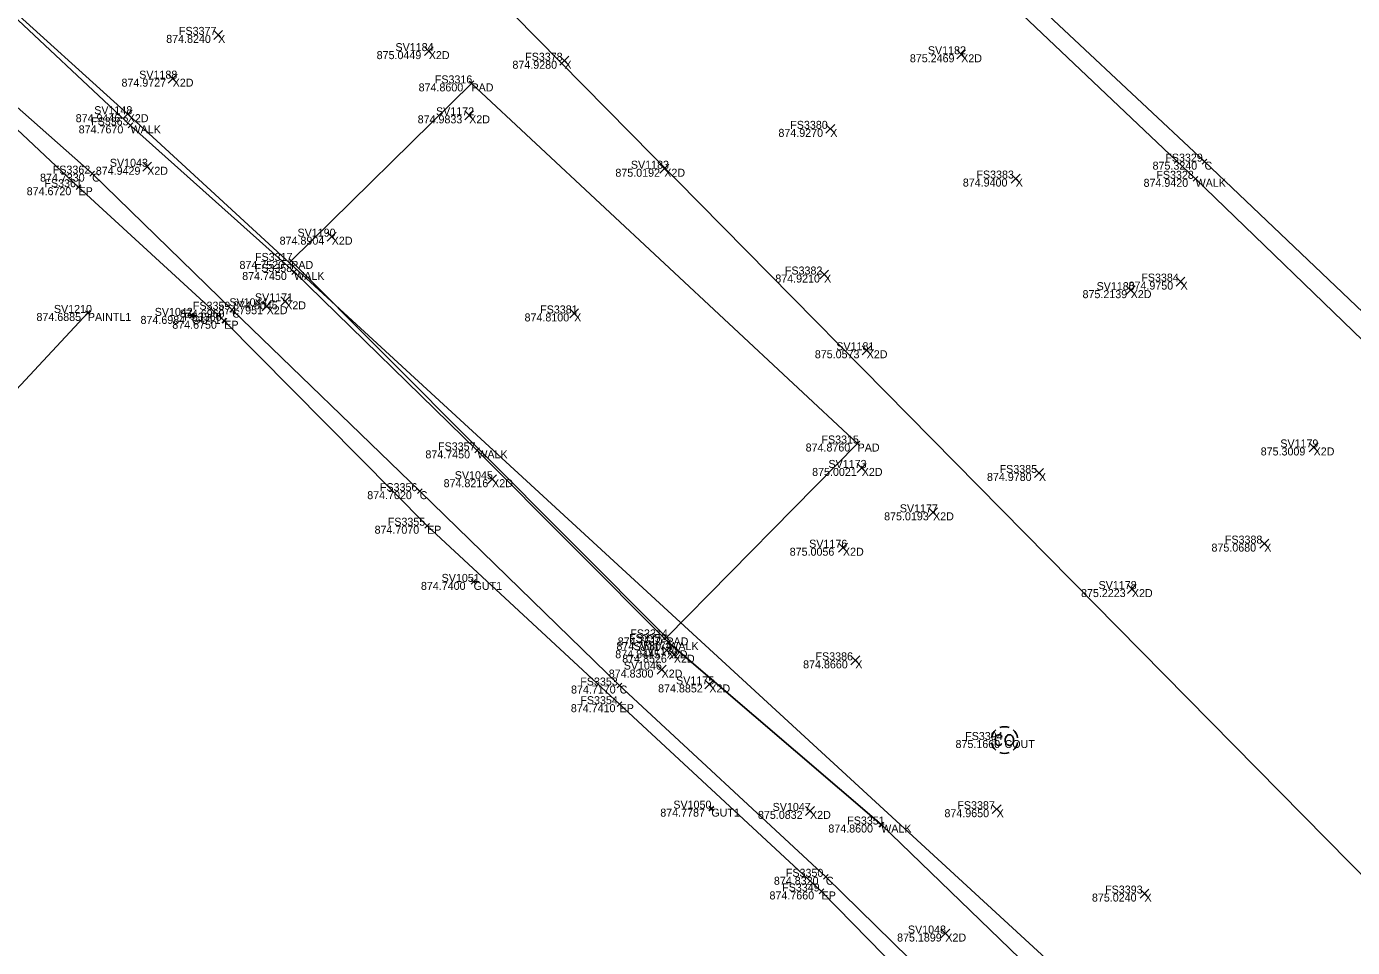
# Model space of a CAD drawing. Extents: x 1479481 to 1575806, y 316056 to 379927.
# Drawn here: x 1480211.87 to 1480221.81, y 379409.43 to 379416.34 of the extents above; entities that cross this region are included whole.
import ezdxf

# ---------------------------------------------------------------- set-up
doc = ezdxf.new("R2010")
doc.units = 0
for name, color, linetype in [('DR_X_Cells', 7, 'Continuous'), ('PM_X_Crosswalk', 7, 'Continuous'), ('PV_X_Curb', 7, 'Continuous'), ('PV_X_Walk', 7, 'Continuous'), ('RD_X_Concrete_Pad', 7, 'Continuous'), ('SV_X_Random_Point', 7, 'Continuous'), ('SV_X_Shot_Marker', 7, 'Continuous'), ('SV_X_Text_Comment', 7, 'Continuous'), ('SV_X_Text_Elevation', 7, 'Continuous'), ('SV_X_Text_Name', 7, 'Continuous'), ('UT_X_Water', 7, 'Continuous')]:
    doc.layers.add(name, color=color, linetype=linetype)

msp = doc.modelspace()

# ---------------------------------------------------------------- linework, layer by layer
at = {"layer": 'DR_X_Cells'}
msp.add_line((1480219.204, 379410.988), (1480219.204, 379410.988), dxfattribs=at)
for points in [[(1480219.1833, 379411.0123), (1480219.1801, 379411.0192), (1480219.177, 379411.023), (1480219.1738, 379411.0255), (1480219.1713, 379411.0268), (1480219.1644, 379411.028), (1480219.1575, 379411.028), (1480219.1486, 379411.0255), (1480219.1436, 379411.0217), (1480219.1411, 379411.0186), (1480219.1386, 379411.0142), (1480219.1367, 379411.0072), (1480219.136, 379410.9946), (1480219.136, 379410.9852), (1480219.136, 379410.9789), (1480219.1367, 379410.9732), (1480219.1386, 379410.9631), (1480219.1392, 379410.9612), (1480219.1417, 379410.9568), (1480219.1442, 379410.9537), (1480219.1486, 379410.9505), (1480219.1524, 379410.9493), (1480219.1575, 379410.948), (1480219.1631, 379410.948), (1480219.1688, 379410.9486), (1480219.1707, 379410.9493), (1480219.1732, 379410.9505), (1480219.1757, 379410.953), (1480219.1789, 379410.9562), (1480219.1814, 379410.96), (1480219.1833, 379410.9631)], [(1480219.2343, 379411.0274), (1480219.2324, 379411.0268), (1480219.2305, 379411.0261), (1480219.2274, 379411.0242), (1480219.2255, 379411.023), (1480219.2223, 379411.0205), (1480219.2198, 379411.0179), (1480219.2186, 379411.0167), (1480219.2167, 379411.0142), (1480219.2135, 379411.0079), (1480219.211, 379411.0016), (1480219.2097, 379410.9959), (1480219.2091, 379410.9877), (1480219.2097, 379410.9789), (1480219.2116, 379410.9726), (1480219.2135, 379410.9675), (1480219.2148, 379410.965), (1480219.2167, 379410.9619), (1480219.2192, 379410.9587), (1480219.2211, 379410.9568), (1480219.223, 379410.9549), (1480219.2255, 379410.953), (1480219.2286, 379410.9512), (1480219.2343, 379410.9486), (1480219.2375, 379410.948), (1480219.2437, 379410.948), (1480219.2463, 379410.9486), (1480219.2488, 379410.9493), (1480219.2519, 379410.9505), (1480219.2551, 379410.9524), (1480219.257, 379410.9537), (1480219.2589, 379410.9549), (1480219.2608, 379410.9568), (1480219.2626, 379410.9593), (1480219.2639, 379410.9612), (1480219.2652, 379410.9631), (1480219.2664, 379410.965), (1480219.2683, 379410.9688), (1480219.2702, 379410.9732), (1480219.2715, 379410.9782), (1480219.2721, 379410.9827), (1480219.2721, 379410.9833), (1480219.2721, 379410.9877), (1480219.2721, 379410.9915), (1480219.2715, 379410.9965), (1480219.2702, 379411.0016), (1480219.2689, 379411.0053), (1480219.2671, 379411.0097), (1480219.2652, 379411.0135), (1480219.262, 379411.0173), (1480219.2595, 379411.0198), (1480219.257, 379411.0223), (1480219.2545, 379411.0242), (1480219.2507, 379411.0261), (1480219.2469, 379411.0274), (1480219.2431, 379411.028), (1480219.2387, 379411.028), (1480219.2343, 379411.0274)]]:
    msp.add_lwpolyline(points, dxfattribs=at)
for start, end in [(130.0806, 170.07213), (70.05767, 110.10608), (10.01689, 50.03919), (190.01689, 230.03919), (310.01144, 350.02638), (250.05767, 290.04731)]:
    msp.add_arc((1480219.204, 379410.9879), 0.1, start, end, dxfattribs=at)
at = {"layer": 'PM_X_Crosswalk'}
msp.add_lwpolyline([(1480185.279, 379385.1136), (1480212.329, 379414.1927)], dxfattribs=at)
at = {"layer": 'PV_X_Curb'}
for points in [[(1480121.053, 379501.135), (1480146.64, 379476.9091), (1480171.177, 379454.1019), (1480173.021, 379452.2286), (1480182.175, 379443.6752), (1480183.379, 379442.6828), (1480186.184, 379440.0133), (1480186.975, 379439.3628), (1480207.407, 379420.3013), (1480208.809, 379419.22), (1480211.103, 379417.051), (1480212.649, 379415.6), (1480213.876, 379414.5), (1480215.25, 379413.1614), (1480216.682, 379411.723), (1480218.279, 379410.354), (1480219.521, 379409.154), (1480220.533, 379408.19), (1480221.926, 379406.75), (1480221.92, 379406.713), (1480221.908, 379406.565), (1480233.156, 379396.15)], [(1480138.714, 379483.7033), (1480170.84, 379453.6811), (1480172.574, 379452.0829), (1480181.867, 379443.3453), (1480182.839, 379442.2172), (1480185.607, 379439.661), (1480186.493, 379438.9546), (1480206.919, 379419.8554), (1480208.298, 379418.862), (1480210.619, 379416.68), (1480212.259, 379415.136), (1480213.352, 379414.134), (1480214.873, 379412.596), (1480216.317, 379411.257), (1480217.832, 379409.852), (1480218.994, 379408.663), (1480220.057, 379407.736), (1480221.503, 379406.348), (1480232.955, 379395.538)], [(1480212.291, 379423.24), (1480213.594, 379422.019), (1480215.401, 379420.362), (1480217.251, 379418.639), (1480219.182, 379416.756), (1480220.704, 379415.328), (1480222.514, 379413.605), (1480224.242, 379411.942), (1480225.485, 379410.67)], [(1480221.623, 379406.45), (1480220.143, 379407.813), (1480219.116, 379408.733), (1480217.864, 379409.962), (1480216.317, 379411.397), (1480214.8179, 379412.8554), (1480213.412, 379414.217), (1480212.361, 379415.238), (1480210.692, 379416.717), (1480208.402, 379418.901)]]:
    msp.add_lwpolyline(points, dxfattribs=at)
at = {"layer": 'PV_X_Walk'}
msp.add_lwpolyline([(1480235.613, 379401.335), (1480225.406, 379410.566), (1480224.081, 379411.883), (1480222.442, 379413.452), (1480220.637, 379415.199), (1480219.083, 379416.674), (1480217.151, 379418.526), (1480213.465, 379422.054), (1480212.267, 379423.157), (1480197.466, 379437.4628), (1480177.803, 379455.9697), (1480154.79, 379476.9674), (1480132.747, 379497.4804), (1480113.376, 379516.7284), (1480110.754, 379519.0396), (1480109.877, 379518.3358), (1480091.944, 379535.2671), (1480093.027, 379536.619), (1480090.219, 379539.2431), (1480090.463, 379539.7253), (1480084.681, 379544.8818), (1480083.843, 379544.144), (1480066.818, 379560.5236), (1480045.662, 379580.0456)], dxfattribs=at)
at = {"layer": 'RD_X_Concrete_Pad'}
msp.add_lwpolyline([(1480216.668, 379411.758), (1480218.102, 379413.213), (1480215.206, 379415.915), (1480213.854, 379414.583)], close=True, dxfattribs=at)
at = {"layer": 'SV_X_Random_Point'}
for p, q in [((1480213.2727, 379416.2456), (1480213.3393, 379416.3124)), ((1480213.2727, 379416.3124), (1480213.3393, 379416.2456)), ((1480214.8527, 379416.1238), (1480214.9193, 379416.1906)), ((1480214.8527, 379416.1906), (1480214.9193, 379416.1238)), ((1480218.8457, 379416.1002), (1480218.9123, 379416.167)), ((1480218.8457, 379416.167), (1480218.9123, 379416.1002)), ((1480215.8697, 379416.0516), (1480215.9363, 379416.1184)), ((1480215.8697, 379416.1184), (1480215.9363, 379416.0516)), ((1480212.9317, 379415.9173), (1480212.9983, 379415.9841)), ((1480212.9317, 379415.9841), (1480212.9983, 379415.9173)), ((1480212.5947, 379415.6507), (1480212.6613, 379415.7175)), ((1480212.5947, 379415.7175), (1480212.6613, 379415.6507)), ((1480215.1557, 379415.6421), (1480215.2223, 379415.7089)), ((1480215.1557, 379415.7089), (1480215.2223, 379415.6421)), ((1480217.8637, 379415.5406), (1480217.9303, 379415.6074)), ((1480217.8637, 379415.6074), (1480217.9303, 379415.5406)), ((1480212.7407, 379415.2561), (1480212.8073, 379415.3229)), ((1480212.7407, 379415.3229), (1480212.8073, 379415.2561)), ((1480216.6187, 379415.2413), (1480216.6853, 379415.3081)), ((1480216.6187, 379415.3081), (1480216.6853, 379415.2413)), ((1480219.2547, 379415.1676), (1480219.3213, 379415.2344)), ((1480219.2547, 379415.2344), (1480219.3213, 379415.1676)), ((1480214.1247, 379414.7316), (1480214.1913, 379414.7984)), ((1480214.1247, 379414.7984), (1480214.1913, 379414.7316)), ((1480217.8177, 379414.4476), (1480217.8843, 379414.5144)), ((1480217.8177, 379414.5144), (1480217.8843, 379414.4476)), ((1480220.4907, 379414.3946), (1480220.5573, 379414.4614)), ((1480220.4907, 379414.4614), (1480220.5573, 379414.3946)), ((1480220.1167, 379414.3302), (1480220.1833, 379414.397)), ((1480220.1167, 379414.397), (1480220.1833, 379414.3302)), ((1480213.6367, 379414.2094), (1480213.7033, 379414.2762)), ((1480213.6367, 379414.2762), (1480213.7033, 379414.2094)), ((1480213.7757, 379414.2462), (1480213.8423, 379414.313)), ((1480213.7757, 379414.313), (1480213.8423, 379414.2462)), ((1480215.9427, 379414.1556), (1480216.0093, 379414.2224)), ((1480215.9427, 379414.2224), (1480216.0093, 379414.1556)), ((1480218.1367, 379413.8793), (1480218.2033, 379413.9461)), ((1480218.1367, 379413.9461), (1480218.2033, 379413.8793)), ((1480221.4887, 379413.1501), (1480221.5553, 379413.2169)), ((1480221.4887, 379413.2169), (1480221.5553, 379413.1501)), ((1480218.0997, 379412.9963), (1480218.1663, 379413.0631)), ((1480218.0997, 379413.0631), (1480218.1663, 379412.9963)), ((1480215.3277, 379412.9118), (1480215.3943, 379412.9786)), ((1480215.3277, 379412.9786), (1480215.3943, 379412.9118)), ((1480219.4287, 379412.9586), (1480219.4953, 379413.0254)), ((1480219.4287, 379413.0254), (1480219.4953, 379412.9586)), ((1480218.6347, 379412.6633), (1480218.7013, 379412.7301)), ((1480218.6347, 379412.7301), (1480218.7013, 379412.6633)), ((1480217.9587, 379412.3976), (1480218.0253, 379412.4644)), ((1480217.9587, 379412.4644), (1480218.0253, 379412.3976)), ((1480221.1187, 379412.4286), (1480221.1853, 379412.4954)), ((1480221.1187, 379412.4954), (1480221.1853, 379412.4286)), ((1480220.1257, 379412.0874), (1480220.1923, 379412.1542)), ((1480220.1257, 379412.1542), (1480220.1923, 379412.0874)), ((1480216.6367, 379411.6285), (1480216.7033, 379411.6953)), ((1480216.6367, 379411.6953), (1480216.7033, 379411.6285)), ((1480216.6907, 379411.595), (1480216.7573, 379411.6618)), ((1480216.6907, 379411.6618), (1480216.7573, 379411.595)), ((1480218.0517, 379411.5526), (1480218.1183, 379411.6194)), ((1480218.0517, 379411.6194), (1480218.1183, 379411.5526)), ((1480216.5987, 379411.4833), (1480216.6653, 379411.5501)), ((1480216.5987, 379411.5501), (1480216.6653, 379411.4833)), ((1480216.9567, 379411.3718), (1480217.0233, 379411.4386)), ((1480216.9567, 379411.4386), (1480217.0233, 379411.3718)), ((1480217.7117, 379410.4229), (1480217.7783, 379410.4897)), ((1480217.7117, 379410.4897), (1480217.7783, 379410.4229)), ((1480219.1117, 379410.4356), (1480219.1783, 379410.5024)), ((1480219.1117, 379410.5024), (1480219.1783, 379410.4356)), ((1480220.2207, 379409.8026), (1480220.2873, 379409.8694)), ((1480220.2207, 379409.8694), (1480220.2873, 379409.8026)), ((1480218.7267, 379409.5027), (1480218.7933, 379409.5695)), ((1480218.7267, 379409.5695), (1480218.7933, 379409.5027))]:
    msp.add_line(p, q, dxfattribs=at)
at = {"layer": 'SV_X_Shot_Marker'}
for p, q in [((1480215.1889, 379415.8967), (1480215.2231, 379415.9333)), ((1480215.2243, 379415.898), (1480215.1877, 379415.9321)), ((1480215.206, 379415.915), (1480215.206, 379415.915)), ((1480212.6308, 379415.6171), (1480212.6672, 379415.5829)), ((1480212.6661, 379415.6182), (1480212.6319, 379415.5818)), ((1480212.649, 379415.6), (1480212.649, 379415.6)), ((1480220.6858, 379415.3451), (1480220.7222, 379415.3109)), ((1480220.7211, 379415.3462), (1480220.6869, 379415.3098)), ((1480212.3789, 379415.2206), (1480212.3431, 379415.2554)), ((1480212.3436, 379415.2201), (1480212.3784, 379415.2559)), ((1480212.361, 379415.238), (1480212.361, 379415.238)), ((1480220.704, 379415.328), (1480220.704, 379415.328)), ((1480212.2408, 379415.1531), (1480212.2772, 379415.1189)), ((1480212.2761, 379415.1542), (1480212.2419, 379415.1178)), ((1480220.655, 379415.1816), (1480220.619, 379415.2164)), ((1480220.6196, 379415.181), (1480220.6544, 379415.217)), ((1480220.637, 379415.199), (1480220.637, 379415.199)), ((1480212.259, 379415.136), (1480212.259, 379415.136)), ((1480213.8718, 379414.6006), (1480213.8362, 379414.5655)), ((1480213.8715, 379414.5652), (1480213.8365, 379414.6008)), ((1480213.854, 379414.583), (1480213.854, 379414.583)), ((1480213.8574, 379414.5167), (1480213.8946, 379414.4833)), ((1480213.8927, 379414.5186), (1480213.8593, 379414.4814)), ((1480213.876, 379414.5), (1480213.876, 379414.5)), ((1480212.3107, 379414.2097), (1480212.3473, 379414.1757)), ((1480212.312, 379414.1744), (1480212.346, 379414.211)), ((1480212.329, 379414.1927), (1480212.329, 379414.1927)), ((1480213.1288, 379414.1871), (1480213.0912, 379414.1541)), ((1480213.0935, 379414.1894), (1480213.1265, 379414.1519)), ((1480213.11, 379414.1706), (1480213.11, 379414.1706)), ((1480213.3336, 379414.1509), (1480213.3704, 379414.1171)), ((1480213.3689, 379414.1524), (1480213.3351, 379414.1156)), ((1480213.43, 379414.1996), (1480213.394, 379414.2344)), ((1480213.3946, 379414.1991), (1480213.4294, 379414.235)), ((1480213.412, 379414.217), (1480213.412, 379414.217)), ((1480213.352, 379414.134), (1480213.352, 379414.134)), ((1480215.2321, 379413.1789), (1480215.2679, 379413.144)), ((1480215.2674, 379413.1794), (1480215.2325, 379413.1435)), ((1480215.25, 379413.1614), (1480215.25, 379413.1614)), ((1480218.0842, 379413.2306), (1480218.1198, 379413.1955)), ((1480218.0845, 379413.1952), (1480218.1195, 379413.2308)), ((1480218.102, 379413.213), (1480218.102, 379413.213)), ((1480214.8359, 379412.8379), (1480214.8, 379412.8728)), ((1480214.8005, 379412.8374), (1480214.8354, 379412.8733)), ((1480214.8179, 379412.8554), (1480214.8179, 379412.8554)), ((1480214.8908, 379412.6136), (1480214.8552, 379412.5784)), ((1480214.8554, 379412.6138), (1480214.8906, 379412.5782)), ((1480214.873, 379412.596), (1480214.873, 379412.596)), ((1480215.2401, 379412.1574), (1480215.2039, 379412.1919)), ((1480215.2047, 379412.1565), (1480215.2393, 379412.1927)), ((1480215.222, 379412.1746), (1480215.222, 379412.1746)), ((1480216.6502, 379411.7756), (1480216.6858, 379411.7405)), ((1480216.6505, 379411.7402), (1480216.6855, 379411.7758)), ((1480216.668, 379411.758), (1480216.668, 379411.758)), ((1480216.6997, 379411.7406), (1480216.6643, 379411.7054)), ((1480216.6644, 379411.7407), (1480216.6996, 379411.7053)), ((1480216.682, 379411.723), (1480216.682, 379411.723)), ((1480216.3353, 379411.38), (1480216.2987, 379411.414)), ((1480216.3, 379411.3787), (1480216.334, 379411.4153)), ((1480216.317, 379411.397), (1480216.317, 379411.397)), ((1480216.2987, 379411.274), (1480216.3353, 379411.24)), ((1480216.334, 379411.2753), (1480216.3, 379411.2387)), ((1480216.317, 379411.257), (1480216.317, 379411.257)), ((1480217.0238, 379410.4898), (1480216.9862, 379410.4568)), ((1480216.9885, 379410.4921), (1480217.0215, 379410.4545)), ((1480217.005, 379410.4733), (1480217.005, 379410.4733)), ((1480218.26, 379410.3703), (1480218.298, 379410.3377)), ((1480218.2953, 379410.373), (1480218.2627, 379410.335)), ((1480218.279, 379410.354), (1480218.279, 379410.354)), ((1480217.8818, 379409.9445), (1480217.8462, 379409.9795)), ((1480217.8465, 379409.9442), (1480217.8815, 379409.9799)), ((1480217.8137, 379409.869), (1480217.8503, 379409.835)), ((1480217.849, 379409.8703), (1480217.815, 379409.8337)), ((1480217.864, 379409.962), (1480217.864, 379409.962)), ((1480217.832, 379409.852), (1480217.832, 379409.852))]:
    msp.add_line(p, q, dxfattribs=at)
at = {"layer": 'UT_X_Water'}
for points in [[(1480049.152, 379568.0166), (1480068.611, 379550.1932), (1480086.403, 379533.4238), (1480090.024, 379530.0794), (1480102.295, 379519.134), (1480111.734, 379511.4732), (1480120.332, 379509.1362), (1480127.535, 379501.6681), (1480127.911, 379496.3954), (1480140.166, 379484.0843), (1480149.088, 379474.708), (1480164.726, 379459.4824), (1480172.622, 379452.5027), (1480197.813, 379429.1106), (1480212.628, 379415.6841), (1480231.592, 379398.2374)], [(1480224.057, 379407.7701), (1480199.329, 379432.8644)]]:
    msp.add_lwpolyline(points, dxfattribs=at)

# ---------------------------------------------------------------- texts
at = {"layer": 'SV_X_Text_Comment'}
for s, p in [('X', (1480213.306, 379416.219)), ('X2D', (1480214.886, 379416.0972)), ('X2D', (1480218.879, 379416.0736)), ('X', (1480215.903, 379416.025)), ('X2D', (1480212.965, 379415.8907)), ('PAD', (1480215.206, 379415.855)), ('X2D', (1480212.628, 379415.6241)), ('X2D', (1480215.189, 379415.6155)), ('WALK', (1480212.649, 379415.54)), ('X', (1480217.897, 379415.514)), ('C', (1480212.361, 379415.178)), ('X2D', (1480212.774, 379415.2295)), ('X2D', (1480216.652, 379415.2147)), ('C', (1480220.704, 379415.268)), ('X', (1480219.288, 379415.141)), ('WALK', (1480220.637, 379415.139)), ('EP', (1480212.259, 379415.076)), ('X2D', (1480214.158, 379414.705)), ('PAD', (1480213.854, 379414.523)), ('WALK', (1480213.876, 379414.44)), ('X', (1480217.851, 379414.421)), ('X2D', (1480220.15, 379414.3036)), ('X', (1480220.524, 379414.368)), ('X2D', (1480213.67, 379414.1828)), ('X2D', (1480213.809, 379414.2196)), ('PAINTL1', (1480212.329, 379414.1327)), ('GUT1', (1480213.11, 379414.1106)), ('C', (1480213.412, 379414.157)), ('X', (1480215.976, 379414.129)), ('EP', (1480213.352, 379414.074)), ('X2D', (1480218.17, 379413.8527)), ('WALK', (1480215.25, 379413.1014)), ('PAD', (1480218.102, 379413.153)), ('X2D', (1480221.522, 379413.1235)), ('X2D', (1480218.133, 379412.9697)), ('X', (1480219.462, 379412.932)), ('C', (1480214.8179, 379412.7954)), ('X2D', (1480215.361, 379412.8852)), ('X2D', (1480218.668, 379412.6367)), ('EP', (1480214.873, 379412.536)), ('X', (1480221.152, 379412.402)), ('X2D', (1480217.992, 379412.371)), ('GUT1', (1480215.222, 379412.1146)), ('X2D', (1480220.159, 379412.0608)), ('PAD', (1480216.668, 379411.698)), ('X2D', (1480216.67, 379411.6019)), ('WALK', (1480216.682, 379411.663)), ('X2D', (1480216.724, 379411.5684)), ('X', (1480218.085, 379411.526)), ('X2D', (1480216.632, 379411.4567)), ('C', (1480216.317, 379411.337)), ('X2D', (1480216.99, 379411.3452)), ('EP', (1480216.317, 379411.197)), ('COUT', (1480219.204, 379410.928)), ('GUT1', (1480217.005, 379410.4133)), ('X', (1480219.145, 379410.409)), ('X2D', (1480217.745, 379410.3963)), ('WALK', (1480218.279, 379410.294)), ('C', (1480217.864, 379409.902)), ('EP', (1480217.832, 379409.792)), ('X', (1480220.254, 379409.776)), ('X2D', (1480218.76, 379409.4761))]:
    msp.add_text(s, height=0.06, dxfattribs=at).set_placement(p)
at = {"layer": 'SV_X_Text_Elevation'}
for s, p in [('874.8240', (1480212.9167, 379416.219)), ('875.0449', (1480214.4949, 379416.0972)), ('875.2469', (1480218.494, 379416.0736)), ('874.9280', (1480215.5133, 379416.025)), ('874.9727', (1480212.5814, 379415.8907)), ('874.8600', (1480214.8097, 379415.855)), ('874.9446', (1480212.2378, 379415.6241)), ('874.9833', (1480214.8026, 379415.6155)), ('874.7670', (1480212.2602, 379415.54)), ('874.9270', (1480217.5082, 379415.514)), ('874.7330', (1480211.9703, 379415.178)), ('874.9429', (1480212.3885, 379415.2295)), ('875.0192', (1480216.2854, 379415.2147)), ('875.3240', (1480220.3143, 379415.268)), ('874.9400', (1480218.8912, 379415.141)), ('874.9420', (1480220.2468, 379415.139)), ('874.6720', (1480211.8702, 379415.076)), ('874.8904', (1480213.7673, 379414.705)), ('874.7520', (1480213.4662, 379414.523)), ('874.7450', (1480213.4867, 379414.44)), ('874.9210', (1480217.4849, 379414.421)), ('875.2139', (1480219.7891, 379414.3036)), ('874.9750', (1480220.1343, 379414.368)), ('874.7951', (1480213.308, 379414.1828)), ('874.8045', (1480213.4183, 379414.2196)), ('874.6885', (1480211.9435, 379414.1327)), ('874.6984', (1480212.724, 379414.1106)), ('874.6960', (1480213.0194, 379414.157)), ('874.8100', (1480215.6042, 379414.129)), ('874.6750', (1480212.9623, 379414.074)), ('875.0573', (1480217.7812, 379413.8527)), ('874.7450', (1480214.8607, 379413.1014)), ('874.8760', (1480217.7123, 379413.153)), ('875.3009', (1480221.1252, 379413.1235)), ('875.0021', (1480217.7611, 379412.9697)), ('874.9780', (1480219.0723, 379412.932)), ('874.7020', (1480214.4244, 379412.7954)), ('874.8216', (1480214.9973, 379412.8852)), ('875.0193', (1480218.301, 379412.6367)), ('874.7070', (1480214.4795, 379412.536)), ('875.0680', (1480220.7561, 379412.402)), ('875.0056', (1480217.5928, 379412.371)), ('874.7400', (1480214.8271, 379412.1146)), ('875.2223', (1480219.7778, 379412.0608)), ('874.7510', (1480216.3029, 379411.698)), ('874.8445', (1480216.2845, 379411.6019)), ('874.7580', (1480216.2932, 379411.663)), ('874.8526', (1480216.3366, 379411.5684)), ('874.8660', (1480217.6934, 379411.526)), ('874.8300', (1480216.2357, 379411.4567)), ('874.7170', (1480215.9528, 379411.337)), ('874.8852', (1480216.6059, 379411.3452)), ('874.7410', (1480215.9514, 379411.197)), ('875.1660', (1480218.8365, 379410.928)), ('874.7787', (1480216.6224, 379410.4133)), ('874.9650', (1480218.7534, 379410.409)), ('875.0832', (1480217.3548, 379410.3963)), ('874.8600', (1480217.8827, 379410.294)), ('874.8320', (1480217.4743, 379409.902)), ('874.7660', (1480217.4413, 379409.792)), ('875.0240', (1480219.8595, 379409.776)), ('875.1899', (1480218.3982, 379409.4761))]:
    msp.add_text(s, height=0.06, dxfattribs=at).set_placement(p)
at = {"layer": 'SV_X_Text_Name'}
for s, p in [('FS3377', (1480213.0122, 379416.279)), ('SV1184', (1480214.6362, 379416.1572)), ('FS3378', (1480215.6087, 379416.085)), ('SV1182', (1480218.6292, 379416.1336)), ('SV1188', (1480212.7142, 379415.9507)), ('FS3316', (1480214.9311, 379415.915)), ('SV1148', (1480212.3767, 379415.6841)), ('SV1172', (1480214.9401, 379415.6755)), ('FS3363', (1480212.3533, 379415.6)), ('FS3380', (1480217.597, 379415.574)), ('SV1043', (1480212.4939, 379415.2895)), ('FS3329', (1480220.4097, 379415.328)), ('FS3362', (1480212.0657, 379415.238)), ('SV1183', (1480216.4017, 379415.2747)), ('FS3383', (1480218.9932, 379415.201)), ('FS3328', (1480220.3427, 379415.199)), ('FS3361', (1480212.0032, 379415.136)), ('SV1190', (1480213.9015, 379414.765)), ('FS3317', (1480213.5829, 379414.583)), ('FS3358', (1480213.5807, 379414.5)), ('FS3382', (1480217.5567, 379414.481)), ('FS3384', (1480220.2297, 379414.428)), ('SV1180', (1480219.8945, 379414.3636)), ('SV1210', (1480212.0744, 379414.1927)), ('FS3359', (1480213.1167, 379414.217)), ('SV1044', (1480213.3904, 379414.2428)), ('SV1171', (1480213.5822, 379414.2796)), ('FS3381', (1480215.7212, 379414.189)), ('SV1042', (1480212.8304, 379414.1706)), ('FS3360', (1480213.0511, 379414.134)), ('SV1181', (1480217.9422, 379413.9127)), ('FS3315', (1480217.8309, 379413.213)), ('FS3357', (1480214.9552, 379413.1614)), ('SV1179', (1480221.2722, 379413.1835)), ('SV1173', (1480217.8836, 379413.0297)), ('FS3385', (1480219.1672, 379412.992)), ('SV1045', (1480215.0809, 379412.9452)), ('FS3356', (1480214.5194, 379412.8554)), ('SV1177', (1480218.4186, 379412.6967)), ('FS3355', (1480214.5782, 379412.596)), ('SV1176', (1480217.7389, 379412.431)), ('FS3388', (1480220.8567, 379412.462)), ('SV1051', (1480214.9823, 379412.1746)), ('SV1178', (1480219.9092, 379412.1208)), ('FS3352', (1480216.3877, 379411.723)), ('FS3314', (1480216.3973, 379411.758)), ('SV1174', (1480216.4211, 379411.6619)), ('SV1170', (1480216.4694, 379411.6284)), ('SV1046', (1480216.3481, 379411.5167)), ('FS3386', (1480217.7864, 379411.586)), ('SV1175', (1480216.7406, 379411.4052)), ('FS3353', (1480216.0222, 379411.397)), ('FS3354', (1480216.0227, 379411.257)), ('FS3394', (1480218.9087, 379410.988)), ('SV1050', (1480216.7202, 379410.4733)), ('SV1047', (1480217.4649, 379410.4563)), ('FS3387', (1480218.8502, 379410.469)), ('FS3351', (1480218.0242, 379410.354)), ('FS3350', (1480217.564, 379409.962)), ('FS3349', (1480217.5363, 379409.852)), ('FS3393', (1480219.9583, 379409.836)), ('SV1048', (1480218.4794, 379409.5361))]:
    msp.add_text(s, height=0.06, dxfattribs=at).set_placement(p)

doc.saveas('drawing.dxf')
